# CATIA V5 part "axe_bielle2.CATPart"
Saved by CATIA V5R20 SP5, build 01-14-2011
Part number: axe_bielle2
Bounding box of the stored display mesh (mm): x -10 to 10, y -1 to 1, z -0.951 to 0.951
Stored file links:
  F:\PROJ IAO\CATIA\axe_bielle2.CATPart
  F:\PROJ IAO\CATIA\Assemblage.CATProduct
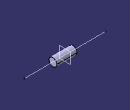
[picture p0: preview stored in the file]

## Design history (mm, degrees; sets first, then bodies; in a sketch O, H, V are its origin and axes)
Set1
  Plane1: linked copy from another document
  Line1: linked copy from another document
Body1 (main body)
  Sketch1 on Plane1, origin (0, 0, 0), H (0, 1, 0), V (0, 0, 1)
    circle A1 centre (0, 0) radius 1
    point P1 (-1, 0)
    radius A1 = 1
    coincidence: A1 P1, P1 H
  Pad1: profile Sketch1, direction (1, 0, 0), length 3
  Pad2 "Extrusion.2": profile start face of Pad1, direction along Line1, length 3, opposite side length 2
